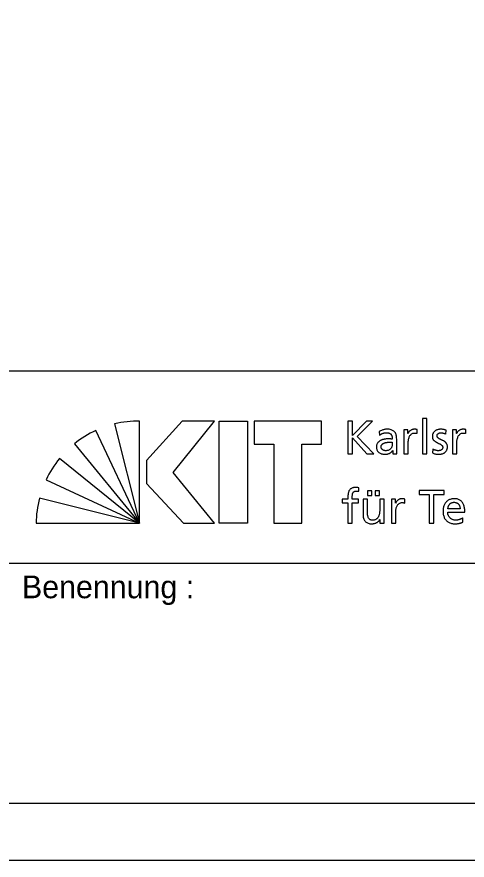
# Model space of a CAD drawing. Extents: x 0 to 4.2, y 0 to 5.94.
# Drawn here: x 2.433 to 3.227, y 0 to 1.485 of the extents above; entities that cross this region are included whole.
import ezdxf

# ---------------------------------------------------------------- set-up
doc = ezdxf.new("R2010")
doc.units = 0
doc.layers.add('90_Plankopf', color=7, linetype='Continuous')

msp = doc.modelspace()

# ---------------------------------------------------------------- linework, layer by layer
at = {"layer": '90_Plankopf'}
for p, q in [((0.5, 0.8614), (4.1, 0.8614)), ((2.6496, 0.5933), (2.6496, 0.7733)), ((3.0162, 0.7733), (3.0162, 0.7157)), ((2.6055, 0.7683), (2.6496, 0.5933)), ((3.1385, 0.7513), (3.1385, 0.7582)), ((3.2242, 0.7513), (3.2242, 0.7582)), ((2.6496, 0.5933), (2.5727, 0.7566)), ((3.0716, 0.7548), (3.072, 0.7482)), ((3.1891, 0.7504), (3.1898, 0.7572)), ((2.5349, 0.7333), (2.6496, 0.5933)), ((3.0946, 0.7358), (3.0946, 0.7321)), ((3.1024, 0.724), (3.1024, 0.7414)), ((3.0162, 0.7157), (3.0244, 0.7157)), ((3.0501, 0.7157), (3.0622, 0.7157)), ((3.1659, 0.724), (3.1655, 0.717)), ((2.6496, 0.5933), (2.5087, 0.7073)), ((2.4848, 0.6699), (2.6496, 0.5933)), ((3.0355, 0.6495), (3.0358, 0.6557)), ((2.6496, 0.5933), (2.4732, 0.6374)), ((3.1165, 0.6289), (3.1165, 0.6358)), ((3.2141, 0.6184), (3.1923, 0.6184)), ((3.1923, 0.6126), (3.2224, 0.6126)), ((3.2192, 0.5951), (3.2192, 0.6028)), ((2.4673, 0.5933), (2.6496, 0.5933)), ((2.173, 0.523), (4.1, 0.523))]:
    msp.add_line(p, q, dxfattribs=at)
for points in [[(0, 0), (4.2, 0), (4.2, 5.94), (0, 5.94)], [(0.5, 5.84), (4.1, 5.84), (4.1, 0.1), (0.5, 0.1)], [(2.7813, 0.7733), (2.7247, 0.7733), (2.6615, 0.7036), (2.6615, 0.6634), (2.7268, 0.5933), (2.7817, 0.5933), (2.7084, 0.6829)], [(2.8394, 0.7733), (2.8394, 0.5933), (2.79, 0.5933), (2.79, 0.7733)], [(2.8512, 0.7733), (2.8512, 0.7328), (2.886, 0.7328), (2.886, 0.5933), (2.9354, 0.5933), (2.9354, 0.7328), (2.9702, 0.7328), (2.9702, 0.7733)]]:
    msp.add_lwpolyline(points, close=True, dxfattribs=at)
for points in [[(3.0622, 0.7157), (3.0329, 0.7461), (3.06, 0.7733), (3.049, 0.7733), (3.0244, 0.748), (3.0244, 0.7733), (3.0162, 0.7733)], [(3.1476, 0.7157), (3.1554, 0.7157), (3.1554, 0.7776), (3.1476, 0.7776), (3.1476, 0.7157)], [(3.1224, 0.7513), (3.1223, 0.7513), (3.1223, 0.7578), (3.115, 0.7578), (3.115, 0.7157), (3.1228, 0.7157), (3.1228, 0.7349)], [(3.2081, 0.7513), (3.208, 0.7513), (3.208, 0.7578), (3.2007, 0.7578), (3.2007, 0.7157), (3.2085, 0.7157), (3.2085, 0.7349)], [(3.0244, 0.7157), (3.0244, 0.7439), (3.0501, 0.7157)], [(3.0953, 0.7212), (3.0954, 0.7212), (3.0954, 0.7157), (3.1027, 0.7157)], [(3.0165, 0.6393), (3.0165, 0.6354), (3.0066, 0.6354), (3.0066, 0.6292), (3.0165, 0.6292), (3.0165, 0.5933), (3.0242, 0.5933), (3.0242, 0.6292), (3.0354, 0.6292), (3.0354, 0.6354), (3.0242, 0.6354), (3.0242, 0.64)], [(3.0511, 0.6501), (3.0511, 0.6419), (3.0588, 0.6419), (3.0588, 0.6501), (3.0511, 0.6501)], [(3.0646, 0.6501), (3.0646, 0.6419), (3.0724, 0.6419), (3.0724, 0.6501), (3.0646, 0.6501)], [(3.1598, 0.5933), (3.1681, 0.5933), (3.1681, 0.6437), (3.186, 0.6437), (3.186, 0.6509), (3.1419, 0.6509), (3.1419, 0.6437), (3.1598, 0.6437), (3.1598, 0.5933)], [(3.0508, 0.6136), (3.0508, 0.6354), (3.0431, 0.6354), (3.0431, 0.6104)], [(3.0803, 0.5933), (3.0803, 0.6354), (3.0725, 0.6354), (3.0725, 0.6159)], [(3.1004, 0.6289), (3.1003, 0.6289), (3.1003, 0.6354), (3.093, 0.6354), (3.093, 0.5933), (3.1008, 0.5933), (3.1008, 0.6125)], [(3.0726, 0.6), (3.0728, 0.6), (3.0728, 0.5933), (3.0803, 0.5933)]]:
    msp.add_lwpolyline(points, dxfattribs=at)
for centre, start, end in [((2.649, 0.5827), 89.8053, 103.1895), ((2.6532, 0.584), 115.0126, 128.3968), ((2.6563, 0.5869), 140.7898, 154.174), ((2.6578, 0.5904), 165.7222, 179.1064)]:
    msp.add_arc(centre, 0.1906, start, end, dxfattribs=at)
for points in [[(3.1024, 0.7414), (3.1024, 0.7452), (3.1018, 0.7484), (3.1007, 0.751), (3.0995, 0.7536), (3.0977, 0.7555), (3.0952, 0.7568), (3.0927, 0.7581), (3.0894, 0.7588), (3.0854, 0.7588), (3.0828, 0.7588), (3.0803, 0.7584), (3.078, 0.7577), (3.0756, 0.757), (3.0735, 0.756), (3.0716, 0.7548)], [(3.1385, 0.7582), (3.138, 0.7583), (3.1375, 0.7584), (3.137, 0.7585), (3.1365, 0.7586), (3.136, 0.7587), (3.1354, 0.7587), (3.1348, 0.7588), (3.1342, 0.7588), (3.1334, 0.7588), (3.1319, 0.7588), (3.1305, 0.7585), (3.129, 0.7578), (3.1276, 0.7572), (3.1264, 0.7563), (3.1252, 0.7552), (3.1241, 0.7541), (3.1231, 0.7528), (3.1224, 0.7513)], [(3.1898, 0.7572), (3.1883, 0.7576), (3.1867, 0.758), (3.1852, 0.7583), (3.1836, 0.7586), (3.1819, 0.7588), (3.1801, 0.7588), (3.1781, 0.7588), (3.1761, 0.7585), (3.1743, 0.758), (3.1725, 0.7575), (3.1709, 0.7567), (3.1696, 0.7556), (3.1682, 0.7545), (3.1672, 0.7532), (3.1664, 0.7516), (3.1657, 0.7499), (3.1653, 0.748), (3.1653, 0.7458), (3.1653, 0.7442), (3.1656, 0.7427), (3.1663, 0.7415), (3.1669, 0.7403), (3.1678, 0.7392), (3.1689, 0.7383), (3.17, 0.7374), (3.1712, 0.7366), (3.1725, 0.7359), (3.1738, 0.7352), (3.1751, 0.7345), (3.1763, 0.7339), (3.1776, 0.7333), (3.1788, 0.7327), (3.1799, 0.732), (3.181, 0.7314), (3.1819, 0.7307), (3.1825, 0.7299), (3.1832, 0.7291), (3.1835, 0.7281), (3.1835, 0.727), (3.1835, 0.7259), (3.1833, 0.7249), (3.1828, 0.7242), (3.1823, 0.7234), (3.1817, 0.7228), (3.1809, 0.7223), (3.1801, 0.7218), (3.1793, 0.7215), (3.1783, 0.7213), (3.1774, 0.7211), (3.1765, 0.721), (3.1756, 0.721), (3.1748, 0.721), (3.1739, 0.7211), (3.1728, 0.7213), (3.1717, 0.7215), (3.1705, 0.7219), (3.1693, 0.7223), (3.1681, 0.7228), (3.167, 0.7233), (3.1659, 0.724)], [(3.2242, 0.7582), (3.2237, 0.7583), (3.2232, 0.7584), (3.2227, 0.7585), (3.2222, 0.7586), (3.2217, 0.7587), (3.2211, 0.7587), (3.2205, 0.7588), (3.2199, 0.7588), (3.2191, 0.7588), (3.2176, 0.7588), (3.2162, 0.7585), (3.2147, 0.7578), (3.2133, 0.7572), (3.2121, 0.7563), (3.2109, 0.7552), (3.2098, 0.7541), (3.2088, 0.7528), (3.2081, 0.7513)], [(3.072, 0.7482), (3.0731, 0.7491), (3.0743, 0.7499), (3.0756, 0.7505), (3.0769, 0.7512), (3.0783, 0.7517), (3.0798, 0.752), (3.0813, 0.7524), (3.0827, 0.7525), (3.0842, 0.7525), (3.0868, 0.7525), (3.0888, 0.7521), (3.0904, 0.7513), (3.0919, 0.7505), (3.093, 0.7493), (3.0936, 0.7476), (3.0943, 0.746), (3.0946, 0.744), (3.0946, 0.7415)], [(3.1228, 0.7349), (3.1228, 0.7384), (3.1233, 0.7415), (3.1242, 0.744), (3.1251, 0.7466), (3.1265, 0.7486), (3.1282, 0.7499), (3.1299, 0.7513), (3.1319, 0.752), (3.1342, 0.752), (3.1349, 0.752), (3.1356, 0.752), (3.1364, 0.7519), (3.1371, 0.7518), (3.1378, 0.7516), (3.1385, 0.7513)], [(3.1655, 0.717), (3.1673, 0.7161), (3.1692, 0.7155), (3.1712, 0.7152), (3.1731, 0.7148), (3.1751, 0.7147), (3.1771, 0.7147), (3.179, 0.7147), (3.1808, 0.715), (3.1825, 0.7155), (3.1843, 0.716), (3.1859, 0.7168), (3.1873, 0.7179), (3.1886, 0.719), (3.1897, 0.7204), (3.1905, 0.722), (3.1914, 0.7237), (3.1918, 0.7256), (3.1918, 0.7278), (3.1918, 0.7298), (3.1914, 0.7314), (3.1908, 0.7327), (3.1901, 0.734), (3.1892, 0.7352), (3.1882, 0.7361), (3.1871, 0.737), (3.1859, 0.7378), (3.1846, 0.7385), (3.1833, 0.7392), (3.182, 0.7398), (3.1807, 0.7403), (3.1794, 0.7409), (3.1782, 0.7415), (3.1772, 0.7421), (3.1761, 0.7428), (3.1752, 0.7435), (3.1745, 0.7443), (3.1739, 0.7452), (3.1736, 0.7462), (3.1735, 0.7474), (3.1736, 0.7486), (3.1739, 0.7495), (3.1746, 0.7503), (3.1753, 0.751), (3.1762, 0.7516), (3.1773, 0.752), (3.1784, 0.7524), (3.1796, 0.7525), (3.181, 0.7525), (3.1814, 0.7525), (3.182, 0.7525), (3.1828, 0.7524), (3.1835, 0.7522), (3.1843, 0.7521), (3.1851, 0.7519), (3.1859, 0.7517), (3.1867, 0.7514), (3.1874, 0.7512), (3.1881, 0.7509), (3.1887, 0.7507), (3.1891, 0.7504)], [(3.2085, 0.7349), (3.2085, 0.7384), (3.209, 0.7415), (3.2099, 0.744), (3.2108, 0.7466), (3.2122, 0.7486), (3.2139, 0.7499), (3.2156, 0.7513), (3.2176, 0.752), (3.2199, 0.752), (3.2206, 0.752), (3.2213, 0.752), (3.2221, 0.7519), (3.2228, 0.7518), (3.2235, 0.7516), (3.2242, 0.7513)], [(3.0946, 0.7415), (3.0936, 0.7416), (3.0927, 0.7416), (3.0918, 0.7417), (3.0909, 0.7417), (3.09, 0.7417), (3.0892, 0.7417), (3.0883, 0.7417), (3.0874, 0.7417), (3.0864, 0.7417), (3.0847, 0.7417), (3.083, 0.7416), (3.0813, 0.7413), (3.0795, 0.741), (3.0777, 0.7405), (3.076, 0.7399), (3.0743, 0.7392), (3.0728, 0.7384), (3.0714, 0.7373), (3.07, 0.7362), (3.0689, 0.7349), (3.0681, 0.7334), (3.0672, 0.7318), (3.0668, 0.73), (3.0668, 0.7278), (3.0668, 0.7248), (3.0675, 0.7223), (3.0688, 0.7204), (3.0701, 0.7184), (3.0719, 0.717), (3.0742, 0.7161), (3.0765, 0.7152), (3.0792, 0.7147), (3.0822, 0.7147), (3.084, 0.7147), (3.0856, 0.715), (3.087, 0.7154), (3.0884, 0.7158), (3.0897, 0.7163), (3.0907, 0.717), (3.0918, 0.7176), (3.0927, 0.7183), (3.0935, 0.7191), (3.0942, 0.7198), (3.0948, 0.7205), (3.0953, 0.7212)], [(3.0946, 0.7321), (3.0946, 0.73), (3.0942, 0.7281), (3.0933, 0.7264), (3.0924, 0.7247), (3.0911, 0.7234), (3.0893, 0.7225), (3.0876, 0.7215), (3.0854, 0.721), (3.0829, 0.721), (3.082, 0.721), (3.0811, 0.7212), (3.0802, 0.7214), (3.0793, 0.7217), (3.0784, 0.7222), (3.0776, 0.7227), (3.0769, 0.7233), (3.0762, 0.7241), (3.0758, 0.7249), (3.0753, 0.7257), (3.0751, 0.7267), (3.075, 0.7278), (3.0751, 0.7293), (3.0754, 0.7306), (3.0762, 0.7315), (3.0769, 0.7325), (3.0778, 0.7333), (3.079, 0.7339), (3.0801, 0.7345), (3.0814, 0.7349), (3.0827, 0.7352), (3.084, 0.7355), (3.0853, 0.7357), (3.0865, 0.7358), (3.0877, 0.7359), (3.0888, 0.7359), (3.0897, 0.7359), (3.0905, 0.7359), (3.0913, 0.7359), (3.0921, 0.7359), (3.093, 0.7358), (3.0938, 0.7358), (3.0946, 0.7358)], [(3.1027, 0.7157), (3.1026, 0.7161), (3.1026, 0.7167), (3.1025, 0.7173), (3.1025, 0.718), (3.1024, 0.7189), (3.1024, 0.72), (3.1024, 0.7211), (3.1024, 0.7224), (3.1024, 0.724)], [(3.0358, 0.6557), (3.035, 0.6558), (3.0342, 0.656), (3.0334, 0.6561), (3.0325, 0.6562), (3.0316, 0.6562), (3.0306, 0.6562), (3.0278, 0.6562), (3.0254, 0.6558), (3.0236, 0.655), (3.0217, 0.6542), (3.0203, 0.6531), (3.0192, 0.6516), (3.0182, 0.6501), (3.0175, 0.6483), (3.0171, 0.6463), (3.0167, 0.6442), (3.0165, 0.6419), (3.0165, 0.6393)], [(3.0242, 0.64), (3.0242, 0.6414), (3.0243, 0.6427), (3.0245, 0.6439), (3.0246, 0.6451), (3.025, 0.6462), (3.0255, 0.6471), (3.026, 0.648), (3.0268, 0.6487), (3.0278, 0.6492), (3.0288, 0.6497), (3.0301, 0.6499), (3.0318, 0.6499), (3.0324, 0.6499), (3.0331, 0.6499), (3.0338, 0.6498), (3.0344, 0.6497), (3.035, 0.6496), (3.0355, 0.6495)], [(3.1165, 0.6358), (3.116, 0.6359), (3.1155, 0.636), (3.115, 0.6361), (3.1145, 0.6362), (3.114, 0.6363), (3.1134, 0.6363), (3.1128, 0.6364), (3.1122, 0.6364), (3.1114, 0.6364), (3.1099, 0.6364), (3.1085, 0.6361), (3.107, 0.6354), (3.1056, 0.6348), (3.1044, 0.6339), (3.1032, 0.6328), (3.1021, 0.6317), (3.1011, 0.6304), (3.1004, 0.6289)], [(3.1008, 0.6125), (3.1008, 0.616), (3.1013, 0.6191), (3.1022, 0.6216), (3.1032, 0.6242), (3.1045, 0.6262), (3.1062, 0.6275), (3.1079, 0.6289), (3.1099, 0.6296), (3.1122, 0.6296), (3.1129, 0.6297), (3.1136, 0.6296), (3.1144, 0.6295), (3.1151, 0.6294), (3.1158, 0.6292), (3.1165, 0.6289)], [(3.2224, 0.6126), (3.2224, 0.616), (3.2221, 0.6192), (3.2214, 0.6221), (3.2208, 0.625), (3.2198, 0.6275), (3.2184, 0.6296), (3.2169, 0.6317), (3.215, 0.6334), (3.2126, 0.6346), (3.2102, 0.6358), (3.2073, 0.6364), (3.2038, 0.6364), (3.2008, 0.6364), (3.1981, 0.6359), (3.1957, 0.6348), (3.1933, 0.6338), (3.1912, 0.6323), (3.1895, 0.6304), (3.1877, 0.6285), (3.1864, 0.6263), (3.1855, 0.6237), (3.1846, 0.6211), (3.1841, 0.6183), (3.1841, 0.6151), (3.1841, 0.6117), (3.1845, 0.6086), (3.1854, 0.6058), (3.1862, 0.603), (3.1876, 0.6006), (3.1894, 0.5986), (3.1912, 0.5966), (3.1934, 0.595), (3.1962, 0.594), (3.1989, 0.5929), (3.2021, 0.5924), (3.2059, 0.5923), (3.2082, 0.5924), (3.2101, 0.5925), (3.2117, 0.5928), (3.2133, 0.5931), (3.2147, 0.5935), (3.2159, 0.5939), (3.2171, 0.5943), (3.2182, 0.5947), (3.2192, 0.5951)], [(3.1923, 0.6184), (3.1925, 0.6198), (3.1928, 0.6212), (3.1933, 0.6225), (3.1938, 0.6239), (3.1944, 0.6252), (3.1954, 0.6263), (3.1962, 0.6275), (3.1974, 0.6284), (3.1987, 0.6291), (3.2001, 0.6298), (3.2017, 0.6301), (3.2036, 0.6301), (3.2053, 0.6301), (3.2068, 0.6298), (3.2081, 0.6292), (3.2094, 0.6286), (3.2105, 0.6278), (3.2114, 0.6267), (3.2123, 0.6256), (3.213, 0.6244), (3.2134, 0.623), (3.2139, 0.6216), (3.2141, 0.62), (3.2141, 0.6184)], [(3.0431, 0.6104), (3.0431, 0.6066), (3.0436, 0.6034), (3.0447, 0.6007), (3.0459, 0.598), (3.0476, 0.5959), (3.0499, 0.5945), (3.0522, 0.5931), (3.0552, 0.5924), (3.0588, 0.5923), (3.0608, 0.5924), (3.0627, 0.5927), (3.0645, 0.5933), (3.0663, 0.5939), (3.0679, 0.5948), (3.0693, 0.5959), (3.0707, 0.597), (3.0718, 0.5984), (3.0726, 0.6)], [(3.0725, 0.6159), (3.0725, 0.6134), (3.0723, 0.611), (3.0718, 0.6089), (3.0713, 0.6068), (3.0705, 0.605), (3.0695, 0.6034), (3.0684, 0.6019), (3.0671, 0.6007), (3.0655, 0.5999), (3.0639, 0.599), (3.0619, 0.5986), (3.0597, 0.5986), (3.0575, 0.5987), (3.0557, 0.5994), (3.0544, 0.6005), (3.0531, 0.6016), (3.0522, 0.6033), (3.0516, 0.6055), (3.0511, 0.6076), (3.0508, 0.6104), (3.0508, 0.6136)], [(3.2192, 0.6028), (3.2187, 0.6024), (3.218, 0.602), (3.217, 0.6015), (3.2161, 0.601), (3.2151, 0.6006), (3.2139, 0.6001), (3.2127, 0.5997), (3.2114, 0.5993), (3.2101, 0.599), (3.2088, 0.5988), (3.2075, 0.5986), (3.2062, 0.5986), (3.2043, 0.5986), (3.2026, 0.599), (3.2009, 0.5996), (3.1993, 0.6003), (3.1978, 0.6013), (3.1965, 0.6025), (3.1952, 0.6037), (3.1942, 0.6052), (3.1935, 0.6069), (3.1927, 0.6087), (3.1923, 0.6106), (3.1923, 0.6126)]]:
    msp.add_open_spline(points, degree=3, dxfattribs=at)

# ---------------------------------------------------------------- texts
msp.add_text('Benennung :', height=0.04, dxfattribs=at).set_placement((2.4423, 0.4612))

doc.saveas('drawing.dxf')
